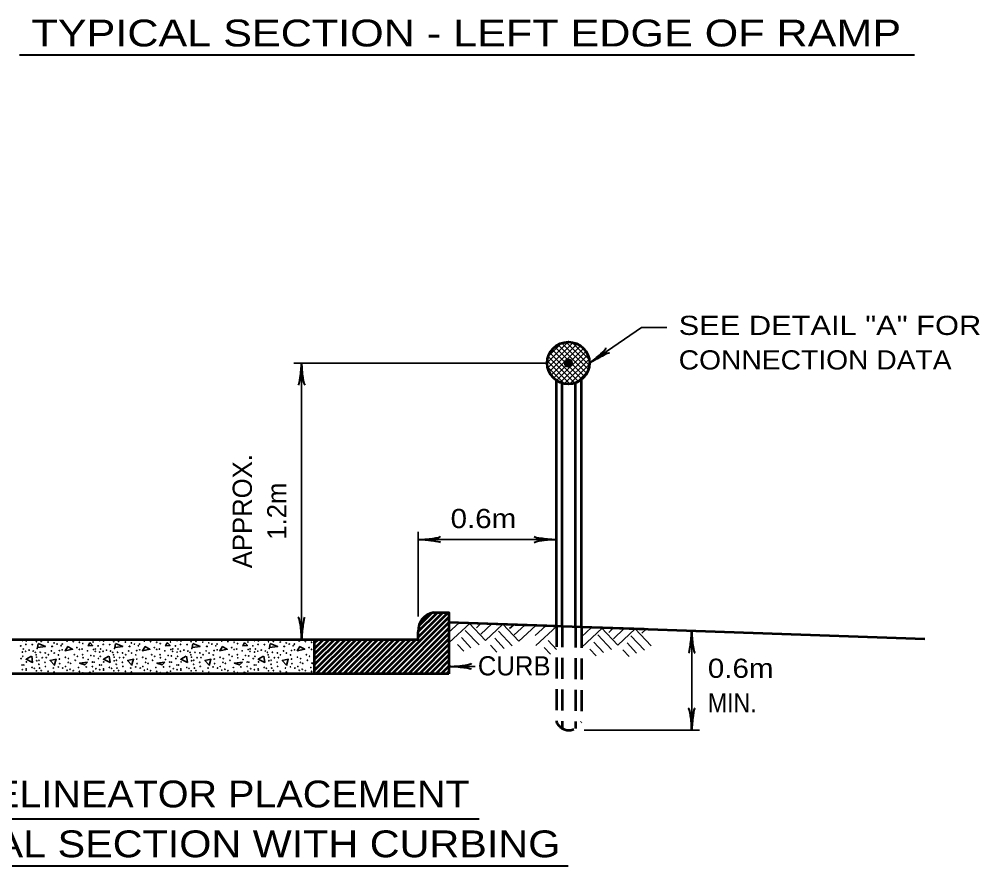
# Model space of a CAD drawing. Extents: x -89 to 766, y -60 to 484.
# Drawn here: x 50.6 to 200.8, y 97.1 to 229.5 of the extents above; entities that cross this region are included whole.
import ezdxf
from ezdxf.enums import TextEntityAlignment as Align

# ---------------------------------------------------------------- set-up
doc = ezdxf.new("R2010")
doc.units = 0
doc.header["$LTSCALE"] = 1.1
doc.linetypes.add('MEDIUM_DASHED', pattern=[4.5, 3, -1.5])
doc.layers.add('1', color=7, linetype='Continuous', lineweight=35)

msp = doc.modelspace()

# ---------------------------------------------------------------- hatches: boundary and pattern name
at = {"layer": '1'}
msp.add_hatch(color=256, dxfattribs=at).paths.add_polyline_path([(137.084, 175.731, 1), (135.884, 175.731, 1)])

# ---------------------------------------------------------------- linework, layer by layer
at = {"layer": '1', "lineweight": 40}
for p, q in [((50.717, 223.916), (190.593, 223.916)), ((40.868, 104.433), (122.541, 104.433)), ((28.02, 97.103), (136.478, 97.103))]:
    msp.add_line(p, q, dxfattribs=at)
at = {"layer": '1'}
for p, q in [((133.185, 175.765), (136.448, 179.028)), ((133.268, 174.999), (137.214, 178.945)), ((133.365, 176.793), (135.422, 178.85)), ((133.485, 174.368), (137.846, 178.729)), ((139.614, 174.704), (135.457, 178.861)), ((139.763, 175.404), (136.155, 179.011)), ((139.731, 176.284), (137.037, 178.978)), ((138.077, 172.846), (133.598, 177.326)), ((133.792, 173.826), (138.388, 178.423)), ((138.583, 173.189), (133.943, 177.829)), ((134.185, 173.371), (138.843, 178.029)), ((139.008, 173.613), (134.365, 178.256)), ((134.652, 172.99), (139.225, 177.563)), ((139.356, 174.113), (134.867, 178.602)), ((138.988, 177.876), (138.631, 178.232)), ((133.184, 175.731), (93.584, 175.731)), ((94.784, 175.731), (94.784, 132.514)), ((136.779, 172.448), (133.202, 176.025)), ((137.484, 172.592), (133.345, 176.73)), ((135.204, 172.693), (139.52, 177.009)), ((135.856, 172.497), (139.717, 176.358)), ((135.887, 172.491), (133.244, 175.134)), ((136.649, 172.441), (139.774, 175.566)), ((137.743, 172.686), (139.532, 174.476)), ((113.028, 136.114), (113.028, 149.314)), ((113.028, 148.114), (134.618, 148.114)), ((119.41, 135.111), (117.771, 133.583)), ((121.113, 135.051), (117.861, 132.019)), ((120.377, 133.924), (122.53, 131.64)), ((120.993, 135.055), (123.539, 132.325)), ((122.816, 134.992), (122.12, 134.32)), ((124.543, 134.931), (122.83, 133.334)), ((126.246, 134.872), (123.539, 132.325)), ((125.584, 133.814), (127.714, 131.531)), ((126.246, 134.872), (128.722, 132.216)), ((127.949, 134.812), (127.303, 134.211)), ((129.675, 134.752), (128.037, 133.224)), ((131.378, 134.693), (128.722, 132.216)), ((132.961, 134.637), (131.323, 133.11)), ((134.664, 134.578), (131.413, 131.546)), ((140.099, 134.388), (138.518, 132.913)), ((141.802, 134.329), (138.518, 131.266)), ((141.682, 134.333), (144.229, 131.602)), ((143.505, 134.269), (142.809, 133.597)), ((145.232, 134.209), (143.519, 132.612)), ((146.935, 134.149), (144.229, 131.602)), ((146.935, 134.149), (149.412, 131.493)), ((148.638, 134.09), (147.993, 133.488)), ((155.768, 118.313), (155.768, 133.847)), ((119.785, 132.792), (121.266, 131.204)), ((124.992, 132.682), (126.474, 131.094)), ((133.337, 132.319), (134.618, 130.945)), ((141.067, 133.202), (143.22, 130.917)), ((146.274, 133.092), (148.404, 130.808)), ((119.147, 131.71), (120.143, 130.666)), ((124.33, 131.601), (125.326, 130.533)), ((132.699, 131.237), (133.695, 130.193)), ((139.837, 130.987), (140.833, 129.944)), ((140.475, 132.07), (141.956, 130.481)), ((145.02, 130.878), (146.015, 129.811)), ((145.682, 131.96), (147.163, 130.371)), ((117.9, 128.273), (121.929, 128.273)), ((53.579, 127.114), (53.607, 127.245)), ((53.607, 127.293), (54.051, 127.114)), ((61.522, 127.114), (61.671, 127.413)), ((61.671, 127.461), (62.001, 127.114)), ((65.675, 127.114), (65.703, 127.245)), ((65.703, 127.293), (66.147, 127.114)), ((73.618, 127.114), (73.767, 127.413)), ((73.767, 127.461), (74.097, 127.114)), ((77.771, 127.114), (77.799, 127.245)), ((77.799, 127.293), (78.243, 127.114)), ((85.714, 127.114), (85.863, 127.413)), ((85.863, 127.461), (86.193, 127.114)), ((89.867, 127.114), (89.895, 127.245)), ((89.895, 127.293), (90.339, 127.114)), ((138.968, 118.313), (156.968, 118.313))]:
    msp.add_line(p, q, dxfattribs=at)
at = {"layer": '1', "lineweight": 53}
for p, q in [((134.618, 134.628), (134.618, 173.008)), ((138.518, 134.491), (138.518, 173.132)), ((135.518, 134.596), (135.518, 172.575)), ((137.618, 134.523), (137.618, 172.632)), ((108.108, 127.114), (117.708, 136.714)), ((113.028, 132.882), (116.86, 136.714)), ((113.029, 133.731), (116.011, 136.714)), ((108.957, 127.114), (117.828, 135.986)), ((113.155, 134.707), (115.073, 136.625)), ((117.828, 135.214), (134.618, 134.628)), ((109.805, 127.114), (117.828, 135.137)), ((110.654, 127.114), (117.828, 134.288)), ((138.518, 134.491), (192.183, 132.618)), ((11.028, 132.514), (96.828, 132.514)), ((96.828, 131.956), (97.386, 132.514)), ((96.828, 131.108), (98.235, 132.514)), ((96.828, 130.259), (99.083, 132.514)), ((96.828, 129.411), (99.932, 132.514)), ((96.828, 128.562), (100.78, 132.514)), ((96.828, 127.713), (101.629, 132.514)), ((97.077, 127.114), (102.477, 132.514)), ((97.926, 127.114), (103.326, 132.514)), ((98.775, 127.114), (104.175, 132.514)), ((99.623, 127.114), (105.023, 132.514)), ((100.472, 127.114), (105.872, 132.514)), ((101.32, 127.114), (106.72, 132.514)), ((102.169, 127.114), (107.569, 132.514)), ((103.017, 127.114), (108.417, 132.514)), ((103.866, 127.114), (109.266, 132.514)), ((104.714, 127.114), (110.114, 132.514)), ((105.563, 127.114), (110.963, 132.514)), ((106.411, 127.114), (111.811, 132.514)), ((107.26, 127.114), (112.66, 132.514)), ((111.502, 127.114), (117.828, 133.44)), ((112.351, 127.114), (117.828, 132.591)), ((113.2, 127.114), (117.828, 131.743)), ((114.048, 127.114), (117.828, 130.894)), ((114.897, 127.114), (117.828, 130.046)), ((115.745, 127.114), (117.828, 129.197)), ((116.594, 127.114), (117.828, 128.349)), ((96.828, 127.114), (11.028, 127.114)), ((117.442, 127.114), (117.828, 127.5))]:
    msp.add_line(p, q, dxfattribs=at)
at = {"layer": '1', "linetype": 'MEDIUM_DASHED', "lineweight": 53}
for p, q in [((134.618, 134.628), (134.618, 119.628)), ((135.518, 134.596), (135.518, 118.594)), ((137.618, 134.523), (137.618, 118.594)), ((138.518, 134.491), (138.518, 119.628))]:
    msp.add_line(p, q, dxfattribs=at)
at = {"layer": '1'}
for points in [[(139.784, 175.731), (147.939, 181.299), (151.862, 181.299)], [(53.607, 131.853), (54.735, 131.397), (53.487, 131.253), (53.607, 131.805)], [(58.191, 131.397), (58.983, 130.965), (57.807, 130.749), (58.239, 131.421)], [(61.671, 132.021), (62.127, 131.541), (61.431, 131.493), (61.671, 131.973)], [(65.703, 131.853), (66.831, 131.397), (65.583, 131.253), (65.703, 131.805)], [(70.287, 131.397), (71.079, 130.965), (69.903, 130.749), (70.335, 131.421)], [(73.767, 132.021), (74.223, 131.541), (73.527, 131.493), (73.767, 131.973)], [(77.799, 131.853), (78.927, 131.397), (77.679, 131.253), (77.799, 131.805)], [(82.383, 131.397), (83.175, 130.965), (81.999, 130.749), (82.431, 131.421)], [(85.863, 132.021), (86.319, 131.541), (85.623, 131.493), (85.863, 131.973)], [(89.895, 131.853), (91.023, 131.397), (89.775, 131.253), (89.895, 131.805)], [(94.479, 131.397), (95.271, 130.965), (94.095, 130.749), (94.527, 131.421)], [(52.551, 129.885), (51.711, 129.405), (52.743, 128.901), (52.599, 129.909)], [(56.127, 128.445), (56.415, 129.405), (55.479, 129.213), (56.151, 128.493)], [(64.647, 129.885), (63.807, 129.405), (64.839, 128.901), (64.695, 129.909)], [(68.223, 128.445), (68.511, 129.405), (67.575, 129.213), (68.247, 128.493)], [(76.743, 129.885), (75.903, 129.405), (76.935, 128.901), (76.791, 129.909)], [(80.319, 128.445), (80.607, 129.405), (79.671, 129.213), (80.343, 128.493)], [(88.839, 129.885), (87.999, 129.405), (89.031, 128.901), (88.887, 129.909)], [(92.415, 128.445), (92.703, 129.405), (91.767, 129.213), (92.439, 128.493)], [(96.828, 128.858), (96.375, 128.805), (96.828, 128.645)]]:
    msp.add_lwpolyline(points, dxfattribs=at)
at = {"layer": '1', "lineweight": 53}
for points in [[(115.428, 136.714), (117.828, 136.714), (117.828, 127.114)], [(117.828, 135.214), (138.518, 134.491), (148.349, 134.148)], [(117.828, 127.114), (96.828, 127.114), (96.828, 130.114), (96.828, 132.514), (113.028, 132.514), (113.028, 133.714)]]:
    msp.add_lwpolyline(points, dxfattribs=at)
at = {"layer": '1'}
for points in [[(61.335, 128.949), (60.087, 128.805), (60.903, 128.517)], [(73.431, 128.949), (72.183, 128.805), (72.999, 128.517)], [(85.527, 128.949), (84.279, 128.805), (85.095, 128.517)]]:
    msp.add_lwpolyline(points, close=True, dxfattribs=at)
at = {"layer": '1', "lineweight": 53}
msp.add_circle((136.484, 175.731), 3.3, dxfattribs=at)
at = {"layer": '1'}
for centre, radius in [((136.484, 175.731), 0.6), ((51.132, 132.329), 0.0318), ((51.72, 132.466), 0.0318), ((51.736, 132.265), 0.0318), ((53.326, 132.154), 0.0318), ((54.09, 132.201), 0.0318), ((58.129, 132.249), 0.0318), ((58.606, 132.402), 0.0318), ((59.084, 132.169), 0.0318), ((62.201, 132.106), 0.0318), ((62.639, 132.482), 0.0318), ((63.228, 132.329), 0.0318), ((63.816, 132.466), 0.0318), ((63.832, 132.265), 0.0318), ((65.422, 132.154), 0.0318), ((66.186, 132.201), 0.0318), ((70.225, 132.249), 0.0318), ((70.702, 132.402), 0.0318), ((71.18, 132.169), 0.0318), ((74.297, 132.106), 0.0318), ((74.735, 132.482), 0.0318), ((75.324, 132.329), 0.0318), ((75.912, 132.466), 0.0318), ((75.928, 132.265), 0.0318), ((77.518, 132.154), 0.0318), ((78.282, 132.201), 0.0318), ((82.321, 132.249), 0.0318), ((82.798, 132.402), 0.0318), ((83.276, 132.169), 0.0318), ((86.393, 132.106), 0.0318), ((86.831, 132.482), 0.0318), ((87.42, 132.329), 0.0318), ((88.008, 132.466), 0.0318), ((88.024, 132.265), 0.0318), ((89.614, 132.154), 0.0318), ((90.378, 132.201), 0.0318), ((94.417, 132.249), 0.0318), ((94.894, 132.402), 0.0318), ((95.372, 132.169), 0.0318), ((50.877, 131.501), 0.0318), ((51.275, 131.008), 0.0318), ((51.656, 130.658), 0.0318), ((51.688, 131.724), 0.0318), ((52.197, 130.833), 0.0318), ((52.69, 131.708), 0.0318), ((52.833, 130.69), 0.0318), ((53.454, 131.088), 0.0318), ((55.155, 132.09), 0.0318), ((55.68, 130.706), 0.0318), ((55.76, 131.406), 0.0318), ((55.823, 131.406), 0.0318), ((56.094, 131.963), 0.0318), ((56.571, 131.772), 0.0318), ((56.921, 130.77), 0.0318), ((57.191, 131.517), 0.0318), ((57.382, 131.772), 0.0318), ((57.382, 130.881), 0.0318), ((59.672, 131.231), 0.0318), ((60.054, 132.058), 0.0318), ((60.054, 130.945), 0.0318), ((60.467, 130.992), 0.0318), ((60.594, 131.851), 0.0318), ((61.326, 130.722), 0.0318), ((62.264, 130.929), 0.0318), ((62.528, 130.642), 0.0318), ((62.544, 131.024), 0.0318), ((62.973, 131.501), 0.0318), ((63.371, 131.008), 0.0318), ((63.752, 130.658), 0.0318), ((63.784, 131.724), 0.0318), ((64.293, 130.833), 0.0318), ((64.786, 131.708), 0.0318), ((64.929, 130.69), 0.0318), ((65.55, 131.088), 0.0318), ((67.251, 132.09), 0.0318), ((67.776, 130.706), 0.0318), ((67.856, 131.406), 0.0318), ((67.919, 131.406), 0.0318), ((68.19, 131.963), 0.0318), ((68.667, 131.772), 0.0318), ((69.017, 130.77), 0.0318), ((69.287, 131.517), 0.0318), ((69.478, 131.772), 0.0318), ((69.478, 130.881), 0.0318), ((71.768, 131.231), 0.0318), ((72.15, 132.058), 0.0318), ((72.15, 130.945), 0.0318), ((72.563, 130.992), 0.0318), ((72.69, 131.851), 0.0318), ((73.422, 130.722), 0.0318), ((74.36, 130.929), 0.0318), ((74.624, 130.642), 0.0318), ((74.64, 131.024), 0.0318), ((75.069, 131.501), 0.0318), ((75.467, 131.008), 0.0318), ((75.848, 130.658), 0.0318), ((75.88, 131.724), 0.0318), ((76.389, 130.833), 0.0318), ((76.882, 131.708), 0.0318), ((77.025, 130.69), 0.0318), ((77.646, 131.088), 0.0318), ((79.347, 132.09), 0.0318), ((79.872, 130.706), 0.0318), ((79.952, 131.406), 0.0318), ((80.015, 131.406), 0.0318), ((80.286, 131.963), 0.0318), ((80.763, 131.772), 0.0318), ((81.113, 130.77), 0.0318), ((81.383, 131.517), 0.0318), ((81.574, 131.772), 0.0318), ((81.574, 130.881), 0.0318), ((83.864, 131.231), 0.0318), ((84.246, 132.058), 0.0318), ((84.246, 130.945), 0.0318), ((84.659, 130.992), 0.0318), ((84.786, 131.851), 0.0318), ((85.518, 130.722), 0.0318), ((86.456, 130.929), 0.0318), ((86.72, 130.642), 0.0318), ((86.736, 131.024), 0.0318), ((87.165, 131.501), 0.0318), ((87.563, 131.008), 0.0318), ((87.944, 130.658), 0.0318), ((87.976, 131.724), 0.0318), ((88.485, 130.833), 0.0318), ((88.978, 131.708), 0.0318), ((89.121, 130.69), 0.0318), ((89.742, 131.088), 0.0318), ((91.443, 132.09), 0.0318), ((91.968, 130.706), 0.0318), ((92.048, 131.406), 0.0318), ((92.111, 131.406), 0.0318), ((92.382, 131.963), 0.0318), ((92.859, 131.772), 0.0318), ((93.209, 130.77), 0.0318), ((93.479, 131.517), 0.0318), ((93.67, 131.772), 0.0318), ((93.67, 130.881), 0.0318), ((95.96, 131.231), 0.0318), ((96.342, 132.058), 0.0318), ((96.342, 130.945), 0.0318), ((96.755, 130.992), 0.0318), ((50.941, 129.513), 0.0318), ((51.148, 130.531), 0.0318), ((51.211, 129.863), 0.0318), ((53.167, 130.483), 0.0318), ((53.295, 130.101), 0.0318), ((53.374, 129.735), 0.0318), ((53.39, 129.163), 0.0318), ((53.74, 129.242), 0.0318), ((53.931, 130.499), 0.0318), ((54.249, 129.64), 0.0318), ((54.71, 130.388), 0.0318), ((54.869, 129.672), 0.0318), ((55.203, 130.117), 0.0318), ((56.125, 130.372), 0.0318), ((56.778, 130.085), 0.0318), ((56.937, 129.433), 0.0318), ((57.859, 129.72), 0.0318), ((58.352, 129.513), 0.0318), ((59.259, 130.117), 0.0318), ((59.402, 129.242), 0.0318), ((59.736, 129.863), 0.0318), ((60.563, 130.117), 0.0318), ((60.626, 129.64), 0.0318), ((61.437, 129.37), 0.0318), ((61.835, 129.99), 0.0318), ((62.337, 129.926), 0.0318), ((63.037, 129.513), 0.0318), ((63.244, 130.531), 0.0318), ((63.307, 129.863), 0.0318), ((65.263, 130.483), 0.0318), ((65.391, 130.101), 0.0318), ((65.47, 129.735), 0.0318), ((65.486, 129.163), 0.0318), ((65.836, 129.242), 0.0318), ((66.027, 130.499), 0.0318), ((66.345, 129.64), 0.0318), ((66.806, 130.388), 0.0318), ((66.965, 129.672), 0.0318), ((67.299, 130.117), 0.0318), ((68.221, 130.372), 0.0318), ((68.874, 130.085), 0.0318), ((69.033, 129.433), 0.0318), ((69.955, 129.72), 0.0318), ((70.448, 129.513), 0.0318), ((71.355, 130.117), 0.0318), ((71.498, 129.242), 0.0318), ((71.832, 129.863), 0.0318), ((72.659, 130.117), 0.0318), ((72.722, 129.64), 0.0318), ((73.533, 129.37), 0.0318), ((73.931, 129.99), 0.0318), ((74.433, 129.926), 0.0318), ((75.133, 129.513), 0.0318), ((75.34, 130.531), 0.0318), ((75.403, 129.863), 0.0318), ((77.359, 130.483), 0.0318), ((77.487, 130.101), 0.0318), ((77.566, 129.735), 0.0318), ((77.582, 129.163), 0.0318), ((77.932, 129.242), 0.0318), ((78.123, 130.499), 0.0318), ((78.441, 129.64), 0.0318), ((78.902, 130.388), 0.0318), ((79.061, 129.672), 0.0318), ((79.395, 130.117), 0.0318), ((80.317, 130.372), 0.0318), ((80.97, 130.085), 0.0318), ((81.129, 129.433), 0.0318), ((82.051, 129.72), 0.0318), ((82.544, 129.513), 0.0318), ((83.451, 130.117), 0.0318), ((83.594, 129.242), 0.0318), ((83.928, 129.863), 0.0318), ((84.755, 130.117), 0.0318), ((84.818, 129.64), 0.0318), ((85.629, 129.37), 0.0318), ((86.027, 129.99), 0.0318), ((86.529, 129.926), 0.0318), ((87.229, 129.513), 0.0318), ((87.436, 130.531), 0.0318), ((87.499, 129.863), 0.0318), ((89.455, 130.483), 0.0318), ((89.583, 130.101), 0.0318), ((89.662, 129.735), 0.0318), ((89.678, 129.163), 0.0318), ((90.028, 129.242), 0.0318), ((90.219, 130.499), 0.0318), ((90.537, 129.64), 0.0318), ((90.998, 130.388), 0.0318), ((91.157, 129.672), 0.0318), ((91.491, 130.117), 0.0318), ((92.413, 130.372), 0.0318), ((93.066, 130.085), 0.0318), ((93.225, 129.433), 0.0318), ((94.147, 129.72), 0.0318), ((94.64, 129.513), 0.0318), ((95.547, 130.117), 0.0318), ((95.69, 129.242), 0.0318), ((96.024, 129.863), 0.0318), ((51.1, 128.51), 0.0318), ((51.132, 127.769), 0.0318), ((51.37, 128.51), 0.0318), ((51.72, 127.906), 0.0318), ((51.736, 127.705), 0.0318), ((51.768, 128.988), 0.0318), ((52.658, 128.129), 0.0318), ((52.992, 127.985), 0.0318), ((53.724, 128.622), 0.0318), ((53.835, 128.017), 0.0318), ((54.09, 127.641), 0.0318), ((54.678, 128.94), 0.0318), ((54.758, 128.288), 0.0318), ((55.982, 128.033), 0.0318), ((56.762, 128.208), 0.0318), ((56.984, 128.717), 0.0318), ((57.461, 128.033), 0.0318), ((57.891, 128.272), 0.0318), ((58.129, 127.689), 0.0318), ((58.304, 128.924), 0.0318), ((58.606, 127.842), 0.0318), ((58.686, 128.749), 0.0318), ((59.084, 127.609), 0.0318), ((59.926, 128.113), 0.0318), ((61.119, 128.208), 0.0318), ((62.089, 128.972), 0.0318), ((62.089, 128.256), 0.0318), ((62.361, 128.953), 0.0318), ((62.639, 127.922), 0.0318), ((63.196, 128.51), 0.0318), ((63.228, 127.769), 0.0318), ((63.466, 128.51), 0.0318), ((63.816, 127.906), 0.0318), ((63.832, 127.705), 0.0318), ((63.864, 128.988), 0.0318), ((64.754, 128.129), 0.0318), ((65.088, 127.985), 0.0318), ((65.82, 128.622), 0.0318), ((65.931, 128.017), 0.0318), ((66.186, 127.641), 0.0318), ((66.774, 128.94), 0.0318), ((66.854, 128.288), 0.0318), ((68.078, 128.033), 0.0318), ((68.858, 128.208), 0.0318), ((69.08, 128.717), 0.0318), ((69.557, 128.033), 0.0318), ((69.987, 128.272), 0.0318), ((70.225, 127.689), 0.0318), ((70.4, 128.924), 0.0318), ((70.702, 127.842), 0.0318), ((70.782, 128.749), 0.0318), ((71.18, 127.609), 0.0318), ((72.022, 128.113), 0.0318), ((73.215, 128.208), 0.0318), ((74.185, 128.972), 0.0318), ((74.185, 128.256), 0.0318), ((74.457, 128.953), 0.0318), ((74.735, 127.922), 0.0318), ((75.292, 128.51), 0.0318), ((75.324, 127.769), 0.0318), ((75.562, 128.51), 0.0318), ((75.912, 127.906), 0.0318), ((75.928, 127.705), 0.0318), ((75.96, 128.988), 0.0318), ((76.85, 128.129), 0.0318), ((77.184, 127.985), 0.0318), ((77.916, 128.622), 0.0318), ((78.027, 128.017), 0.0318), ((78.282, 127.641), 0.0318), ((78.87, 128.94), 0.0318), ((78.95, 128.288), 0.0318), ((80.174, 128.033), 0.0318), ((80.954, 128.208), 0.0318), ((81.176, 128.717), 0.0318), ((81.653, 128.033), 0.0318), ((82.083, 128.272), 0.0318), ((82.321, 127.689), 0.0318), ((82.496, 128.924), 0.0318), ((82.798, 127.842), 0.0318), ((82.878, 128.749), 0.0318), ((83.276, 127.609), 0.0318), ((84.118, 128.113), 0.0318), ((85.311, 128.208), 0.0318), ((86.281, 128.972), 0.0318), ((86.281, 128.256), 0.0318), ((86.553, 128.953), 0.0318), ((86.831, 127.922), 0.0318), ((87.388, 128.51), 0.0318), ((87.42, 127.769), 0.0318), ((87.658, 128.51), 0.0318), ((88.008, 127.906), 0.0318), ((88.024, 127.705), 0.0318), ((88.056, 128.988), 0.0318), ((88.946, 128.129), 0.0318), ((89.28, 127.985), 0.0318), ((90.012, 128.622), 0.0318), ((90.123, 128.017), 0.0318), ((90.378, 127.641), 0.0318), ((90.966, 128.94), 0.0318), ((91.046, 128.288), 0.0318), ((92.27, 128.033), 0.0318), ((93.05, 128.208), 0.0318), ((93.272, 128.717), 0.0318), ((93.749, 128.033), 0.0318), ((94.179, 128.272), 0.0318), ((94.417, 127.689), 0.0318), ((94.592, 128.924), 0.0318), ((94.894, 127.842), 0.0318), ((94.974, 128.749), 0.0318), ((95.372, 127.609), 0.0318), ((96.214, 128.113), 0.0318), ((51.688, 127.164), 0.0318), ((52.69, 127.148), 0.0318), ((53.326, 127.594), 0.0318), ((55.155, 127.53), 0.0318), ((56.094, 127.403), 0.0318), ((56.571, 127.212), 0.0318), ((57.382, 127.212), 0.0318), ((60.054, 127.498), 0.0318), ((60.594, 127.291), 0.0318), ((62.201, 127.546), 0.0318), ((63.784, 127.164), 0.0318), ((64.786, 127.148), 0.0318), ((65.422, 127.594), 0.0318), ((67.251, 127.53), 0.0318), ((68.19, 127.403), 0.0318), ((68.667, 127.212), 0.0318), ((69.478, 127.212), 0.0318), ((72.15, 127.498), 0.0318), ((72.69, 127.291), 0.0318), ((74.297, 127.546), 0.0318), ((75.88, 127.164), 0.0318), ((76.882, 127.148), 0.0318), ((77.518, 127.594), 0.0318), ((79.347, 127.53), 0.0318), ((80.286, 127.403), 0.0318), ((80.763, 127.212), 0.0318), ((81.574, 127.212), 0.0318), ((84.246, 127.498), 0.0318), ((84.786, 127.291), 0.0318), ((86.393, 127.546), 0.0318), ((87.976, 127.164), 0.0318), ((88.978, 127.148), 0.0318), ((89.614, 127.594), 0.0318), ((91.443, 127.53), 0.0318), ((92.382, 127.403), 0.0318), ((92.859, 127.212), 0.0318), ((93.67, 127.212), 0.0318), ((96.342, 127.498), 0.0318)]:
    msp.add_circle(centre, radius, dxfattribs=at)
at = {"layer": '1', "lineweight": 53}
msp.add_arc((115.916, 133.863), 2.892, 99.71788, 182.9625, dxfattribs=at)
at = {"layer": '1'}
for centre, start, end in [((52.992, 132.545), 262.28656, 277.71344), ((65.088, 132.545), 262.28656, 277.71344), ((77.184, 132.545), 262.28656, 277.71344), ((89.28, 132.545), 262.28656, 277.71344), ((96.851, 130.117), 134.79633, 225.20367)]:
    msp.add_arc(centre, 0.0318, start, end, dxfattribs=at)
at = {"layer": '1', "linetype": 'MEDIUM_DASHED', "lineweight": 53}
msp.add_arc((136.568, 120.416), 2.103, 202.01371, 337.98629, dxfattribs=at)
at = {"layer": '1', "lineweight": 40}
for centre, major_axis, ratio, start_param, end_param in [((140.678, 176.743), (-1.664, -1.363), 0.122415, 0.8963533, 3.1415927), ((141.037, 176.279), (-1.86, -1.014), 0.07063, 3.1407148, 5.41811), ((94.53, 174.386), (0.211, 2.108), 0.07063, 3.1407148, 5.41811), ((94.53, 174.386), (0.211, 2.108), 0.07063, 3.1407148, 5.41811), ((95.115, 174.421), (-0.187, 2.143), 0.122415, 0.8963533, 3.1415927), ((95.115, 174.421), (-0.187, 2.143), 0.122415, 0.8963533, 3.1415927), ((114.373, 147.86), (-2.108, 0.211), 0.07063, 3.1407148, 5.41811), ((114.373, 147.86), (-2.108, 0.211), 0.07063, 3.1407148, 5.41811), ((114.338, 148.446), (-2.143, -0.187), 0.122415, 0.8963533, 3.1415927), ((114.338, 148.446), (-2.143, -0.187), 0.122415, 0.8963533, 3.1415927), ((133.309, 147.782), (2.143, 0.187), 0.122415, 0.8963533, 3.1415927), ((133.273, 148.368), (2.108, -0.211), 0.07063, 3.1407148, 5.41811), ((94.452, 133.823), (0.187, -2.143), 0.122415, 0.8963533, 3.1415927), ((95.037, 133.859), (-0.211, -2.108), 0.07063, 3.1407148, 5.41811), ((155.514, 132.503), (0.211, 2.108), 0.07063, 3.1407148, 5.41811), ((155.514, 132.503), (0.211, 2.108), 0.07063, 3.1407148, 5.41811), ((156.1, 132.538), (-0.187, 2.143), 0.122415, 0.8963533, 3.1415927), ((156.1, 132.538), (-0.187, 2.143), 0.122415, 0.8963533, 3.1415927), ((119.245, 128.019), (-2.108, 0.211), 0.07063, 3.1407148, 5.41811), ((119.21, 128.605), (-2.143, -0.187), 0.122415, 0.8963533, 3.1415927), ((155.436, 119.622), (0.187, -2.143), 0.122415, 0.8963533, 3.1415927), ((156.022, 119.657), (-0.211, -2.108), 0.07063, 3.1407148, 5.41811)]:
    msp.add_ellipse(centre, major_axis=major_axis, ratio=ratio, start_param=start_param, end_param=end_param, dxfattribs=at)

# ---------------------------------------------------------------- texts
at = {"layer": '1'}
for s, width, p in [('TYPICAL SECTION - LEFT EDGE OF RAMP', 1.2, (120.534, 225.246)), ('DELINEATOR PLACEMENT', 1.1, (81.578, 106.233)), ('TYPICAL SECTION WITH CURBING', 1.15, (81.578, 98.433))]:
    msp.add_text(s, height=4.2, dxfattribs=dict(at, width=width)).set_placement(p, align=Align.CENTER)
for s, width, p in [('SEE DETAIL "A" FOR', 1.2, (153.732, 180.125)), ('CONNECTION DATA', 1.1, (153.732, 174.725)), ('0.6m', 1.15, (118.079, 149.92)), ('0.6m', 1.15, (158.294, 126.499)), ('MIN.', 0.9, (158.294, 121.099))]:
    msp.add_text(s, height=3, dxfattribs=dict(at, width=width)).set_placement(p)
for s, p in [('APPROX.', (87.01, 152.565)), ('1.2m', (92.41, 152.565))]:
    msp.add_text(s, height=3, rotation=90, dxfattribs=at).set_placement(p, align=Align.CENTER)
msp.add_text('CURB', height=3, dxfattribs=at).set_placement((122.334, 126.878))

doc.saveas('drawing.dxf')
